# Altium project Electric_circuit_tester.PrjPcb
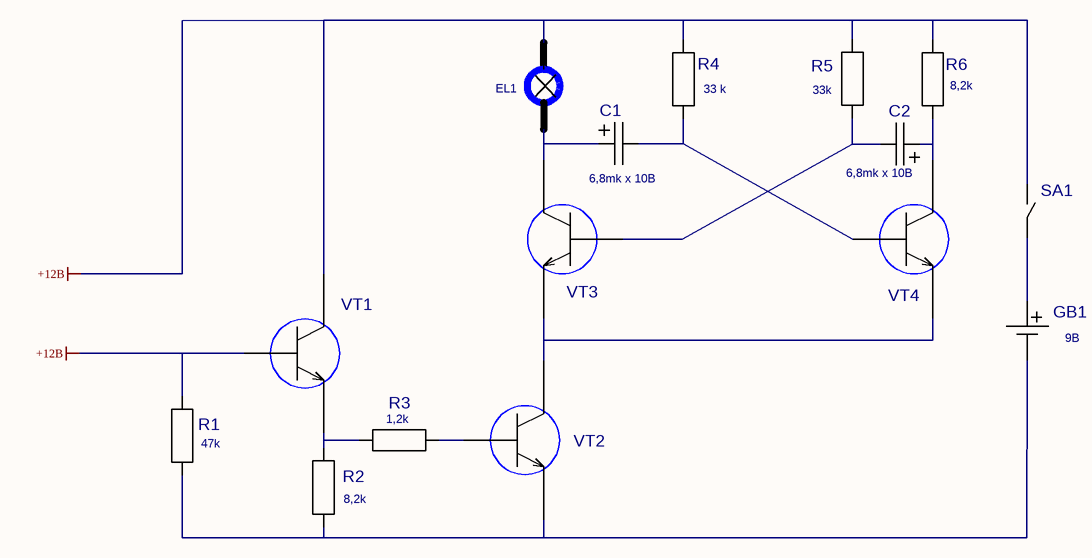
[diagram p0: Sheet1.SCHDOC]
1 sheet, 15 parts. Net scope: global (net labels, ports and power ports of the same name join across sheets).
Board file: Electric_circuit_tester.PcbDoc

## Sheet Sheet1.SCHDOC
size 297 x 209 mm; SheetNumber: 1; SheetTotal: 1

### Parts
C1  value 6,8mk x 10B  [K534A-2]  (hidden comment: K534A-2)
C2  value 6,8mk x 10B  [K534A-2]  (hidden comment: K534A-2)
EL1  СМН6.3-20-2  [HL_MINI]  (value not drawn)
GB1  value 9B  [BH-624 (1X AAA)]  (hidden comment: BH-624 (1X AAA))
R1  value 47k  [C2-33H-1W_17.5MM]  (hidden comment: С2-23-1 ВТ)
R2  value 8,2k  [C2-33H-1W_17.5MM]  (hidden comment: С2-23-1 ВТ)
R3  value 1,2k  [C2-33H-1W_17.5MM]  (hidden comment: С2-23-1 ВТ)
R4  value 33 k  [C2-33H-1W_17.5MM]  (hidden comment: С2-23-1 ВТ)
R5  value 33k  [C2-33H-1W_17.5MM]  (hidden comment: С2-23-1 ВТ)
R6  value 8,2k  [C2-33H-1W_17.5MM]  (hidden comment: С2-23-1 ВТ)
SA1  8AS9M2RE  [8AS9M2RE]  (value not drawn)
VT1  КТ315Б  [KT13]  (value not drawn)
VT2  КТ315Б  [KT13]  (value not drawn)
VT3  КТ315Б  [KT13]  (value not drawn)
VT4  КТ315Б  [KT13]  (value not drawn)

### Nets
+12B: EL1.2 R1.2(I/O1) R4.2(I/O1) R5.2(I/O1) R6.2(I/O1) SA1.1 VT1.2(B) VT1.3(K)
NetC1_1: C1.1(I/OA) EL1.1 VT3.3(K)
NetC1_2: C1.2(I/OB) R4.1(I/O0) VT4.2(B)
NetC2_1: C2.1(I/OA) R6.1(I/O0) VT4.3(K)
NetC2_2: C2.2(I/OB) R5.1(I/O0) VT3.2(B)
NetGB1_1: GB1.1 R1.1(I/O0) R2.1(I/O0) VT2.1(E)
NetGB1_2: GB1.2 SA1.2
NetR2_2: R2.2(I/O1) R3.1(I/O0) VT1.1(E)
NetR3_2: R3.2(I/O1) VT2.2(B)
NetVT2_3: VT2.3(K) VT3.1(E) VT4.1(E)

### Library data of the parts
C1 C2 = K534A-2: PDIF_TY: 11245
